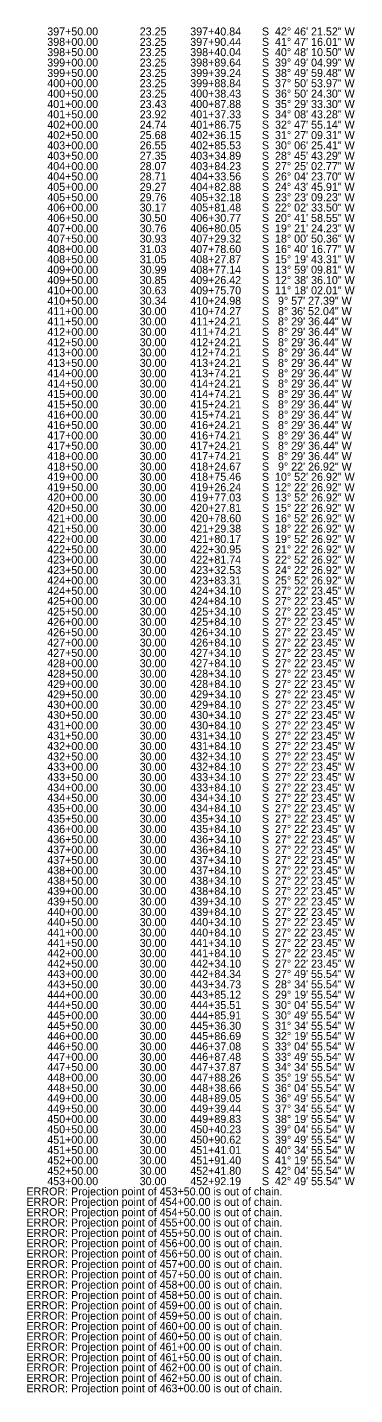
# Model space of a CAD drawing. Extents: x 1602163 to 1612907, y 1087635 to 1096265.
# Drawn here: x 1602163 to 1602409, y 1094083 to 1095108 of the extents above; entities that cross this region are included whole.
import ezdxf

# ---------------------------------------------------------------- set-up
doc = ezdxf.new("R2010")
doc.units = 0
doc.layers.add('RD_SHT_TX', color=7, linetype='Continuous')

msp = doc.modelspace()

# ---------------------------------------------------------------- texts
at = {"layer": 'RD_SHT_TX'}
for s, p in [('       397+50.00              23.25        397+40.84       S  42° 46\' 21.52" W  ', (1602162.4, 1095102.2)), ('       398+00.00              23.25        397+90.44       S  41° 47\' 16.01" W  ', (1602162.4, 1095094.4)), ('       398+50.00              23.25        398+40.04       S  40° 48\' 10.50" W  ', (1602162.4, 1095086.7)), ('       399+00.00              23.25        398+89.64       S  39° 49\' 04.99" W  ', (1602162.4, 1095078.9)), ('       399+50.00              23.25        399+39.24       S  38° 49\' 59.48" W  ', (1602162.4, 1095071.1)), ('       400+00.00              23.25        399+88.84       S  37° 50\' 53.97" W  ', (1602162.4, 1095063.4)), ('       400+50.00              23.25        400+38.43       S  36° 50\' 24.30" W  ', (1602162.4, 1095055.6)), ('       401+00.00              23.43        400+87.88       S  35° 29\' 33.30" W  ', (1602162.4, 1095047.8)), ('       401+50.00              23.92        401+37.33       S  34° 08\' 43.28" W  ', (1602162.4, 1095040.1)), ('       402+00.00              24.74        401+86.75       S  32° 47\' 55.14" W  ', (1602162.4, 1095032.3)), ('       402+50.00              25.68        402+36.15       S  31° 27\' 09.31" W  ', (1602162.4, 1095024.5)), ('       403+00.00              26.55        402+85.53       S  30° 06\' 25.41" W  ', (1602162.4, 1095016.8)), ('       403+50.00              27.35        403+34.89       S  28° 45\' 43.29" W  ', (1602162.4, 1095009)), ('       404+00.00              28.07        403+84.23       S  27° 25\' 02.77" W  ', (1602162.4, 1095001.2)), ('       404+50.00              28.71        404+33.56       S  26° 04\' 23.70" W  ', (1602162.4, 1094993.5)), ('       405+00.00              29.27        404+82.88       S  24° 43\' 45.91" W  ', (1602162.4, 1094985.7)), ('       405+50.00              29.76        405+32.18       S  23° 23\' 09.23" W  ', (1602162.4, 1094977.9)), ('       406+00.00              30.17        405+81.48       S  22° 02\' 33.50" W  ', (1602162.4, 1094970.2)), ('       406+50.00              30.50        406+30.77       S  20° 41\' 58.55" W  ', (1602162.4, 1094962.4)), ('       407+00.00              30.76        406+80.05       S  19° 21\' 24.23" W  ', (1602162.4, 1094954.6)), ('       407+50.00              30.93        407+29.32       S  18° 00\' 50.36" W  ', (1602162.4, 1094946.9)), ('       408+00.00              31.03        407+78.60       S  16° 40\' 16.77" W  ', (1602162.4, 1094939.1)), ('       408+50.00              31.05        408+27.87       S  15° 19\' 43.31" W  ', (1602162.4, 1094931.4)), ('       409+00.00              30.99        408+77.14       S  13° 59\' 09.81" W  ', (1602162.4, 1094923.6)), ('       409+50.00              30.85        409+26.42       S  12° 38\' 36.10" W  ', (1602162.4, 1094915.8)), ('       410+00.00              30.63        409+75.70       S  11° 18\' 02.01" W  ', (1602162.4, 1094908.1)), ('       410+50.00              30.34        410+24.98       S   9° 57\' 27.39" W  ', (1602162.4, 1094900.3)), ('       411+00.00              30.00        410+74.27       S   8° 36\' 52.04" W  ', (1602162.4, 1094892.5)), ('       411+50.00              30.00        411+24.21       S   8° 29\' 36.44" W  ', (1602162.4, 1094884.8)), ('       412+00.00              30.00        411+74.21       S   8° 29\' 36.44" W  ', (1602162.4, 1094877)), ('       412+50.00              30.00        412+24.21       S   8° 29\' 36.44" W  ', (1602162.4, 1094869.2)), ('       413+00.00              30.00        412+74.21       S   8° 29\' 36.44" W  ', (1602162.4, 1094861.5)), ('       413+50.00              30.00        413+24.21       S   8° 29\' 36.44" W  ', (1602162.4, 1094853.7)), ('       414+00.00              30.00        413+74.21       S   8° 29\' 36.44" W  ', (1602162.4, 1094845.9)), ('       414+50.00              30.00        414+24.21       S   8° 29\' 36.44" W  ', (1602162.4, 1094838.2)), ('       415+00.00              30.00        414+74.21       S   8° 29\' 36.44" W  ', (1602162.4, 1094830.4)), ('       415+50.00              30.00        415+24.21       S   8° 29\' 36.44" W  ', (1602162.4, 1094822.6)), ('       416+00.00              30.00        415+74.21       S   8° 29\' 36.44" W  ', (1602162.4, 1094814.9)), ('       416+50.00              30.00        416+24.21       S   8° 29\' 36.44" W  ', (1602162.4, 1094807.1)), ('       417+00.00              30.00        416+74.21       S   8° 29\' 36.44" W  ', (1602162.4, 1094799.3)), ('       417+50.00              30.00        417+24.21       S   8° 29\' 36.44" W  ', (1602162.4, 1094791.6)), ('       418+00.00              30.00        417+74.21       S   8° 29\' 36.44" W  ', (1602162.4, 1094783.8)), ('       418+50.00              30.00        418+24.67       S   9° 22\' 26.92" W  ', (1602162.4, 1094776)), ('       419+00.00              30.00        418+75.46       S  10° 52\' 26.92" W  ', (1602162.4, 1094768.3)), ('       419+50.00              30.00        419+26.24       S  12° 22\' 26.92" W  ', (1602162.4, 1094760.5)), ('       420+00.00              30.00        419+77.03       S  13° 52\' 26.92" W  ', (1602162.4, 1094752.8)), ('       420+50.00              30.00        420+27.81       S  15° 22\' 26.92" W  ', (1602162.4, 1094745)), ('       421+00.00              30.00        420+78.60       S  16° 52\' 26.92" W  ', (1602162.4, 1094737.2)), ('       421+50.00              30.00        421+29.38       S  18° 22\' 26.92" W  ', (1602162.4, 1094729.5)), ('       422+00.00              30.00        421+80.17       S  19° 52\' 26.92" W  ', (1602162.4, 1094721.7)), ('       422+50.00              30.00        422+30.95       S  21° 22\' 26.92" W  ', (1602162.4, 1094713.9)), ('       423+00.00              30.00        422+81.74       S  22° 52\' 26.92" W  ', (1602162.4, 1094706.2)), ('       423+50.00              30.00        423+32.53       S  24° 22\' 26.92" W  ', (1602162.4, 1094698.4)), ('       424+00.00              30.00        423+83.31       S  25° 52\' 26.92" W  ', (1602162.4, 1094690.6)), ('       424+50.00              30.00        424+34.10       S  27° 22\' 23.45" W  ', (1602162.4, 1094682.9)), ('       425+00.00              30.00        424+84.10       S  27° 22\' 23.45" W  ', (1602162.4, 1094675.1)), ('       425+50.00              30.00        425+34.10       S  27° 22\' 23.45" W  ', (1602162.4, 1094667.3)), ('       426+00.00              30.00        425+84.10       S  27° 22\' 23.45" W  ', (1602162.4, 1094659.6)), ('       426+50.00              30.00        426+34.10       S  27° 22\' 23.45" W  ', (1602162.4, 1094651.8)), ('       427+00.00              30.00        426+84.10       S  27° 22\' 23.45" W  ', (1602162.4, 1094644)), ('       427+50.00              30.00        427+34.10       S  27° 22\' 23.45" W  ', (1602162.4, 1094636.3)), ('       428+00.00              30.00        427+84.10       S  27° 22\' 23.45" W  ', (1602162.4, 1094628.5)), ('       428+50.00              30.00        428+34.10       S  27° 22\' 23.45" W  ', (1602162.4, 1094620.7)), ('       429+00.00              30.00        428+84.10       S  27° 22\' 23.45" W  ', (1602162.4, 1094613)), ('       429+50.00              30.00        429+34.10       S  27° 22\' 23.45" W  ', (1602162.4, 1094605.2)), ('       430+00.00              30.00        429+84.10       S  27° 22\' 23.45" W  ', (1602162.4, 1094597.4)), ('       430+50.00              30.00        430+34.10       S  27° 22\' 23.45" W  ', (1602162.4, 1094589.7)), ('       431+00.00              30.00        430+84.10       S  27° 22\' 23.45" W  ', (1602162.4, 1094581.9)), ('       431+50.00              30.00        431+34.10       S  27° 22\' 23.45" W  ', (1602162.4, 1094574.2)), ('       432+00.00              30.00        431+84.10       S  27° 22\' 23.45" W  ', (1602162.4, 1094566.4)), ('       432+50.00              30.00        432+34.10       S  27° 22\' 23.45" W  ', (1602162.4, 1094558.6)), ('       433+00.00              30.00        432+84.10       S  27° 22\' 23.45" W  ', (1602162.4, 1094550.9)), ('       433+50.00              30.00        433+34.10       S  27° 22\' 23.45" W  ', (1602162.4, 1094543.1)), ('       434+00.00              30.00        433+84.10       S  27° 22\' 23.45" W  ', (1602162.4, 1094535.3)), ('       434+50.00              30.00        434+34.10       S  27° 22\' 23.45" W  ', (1602162.4, 1094527.6)), ('       435+00.00              30.00        434+84.10       S  27° 22\' 23.45" W  ', (1602162.4, 1094519.8)), ('       435+50.00              30.00        435+34.10       S  27° 22\' 23.45" W  ', (1602162.4, 1094512)), ('       436+00.00              30.00        435+84.10       S  27° 22\' 23.45" W  ', (1602162.4, 1094504.3)), ('       436+50.00              30.00        436+34.10       S  27° 22\' 23.45" W  ', (1602162.4, 1094496.5)), ('       437+00.00              30.00        436+84.10       S  27° 22\' 23.45" W  ', (1602162.4, 1094488.7)), ('       437+50.00              30.00        437+34.10       S  27° 22\' 23.45" W  ', (1602162.4, 1094481)), ('       438+00.00              30.00        437+84.10       S  27° 22\' 23.45" W  ', (1602162.4, 1094473.2)), ('       438+50.00              30.00        438+34.10       S  27° 22\' 23.45" W  ', (1602162.4, 1094465.4)), ('       439+00.00              30.00        438+84.10       S  27° 22\' 23.45" W  ', (1602162.4, 1094457.7)), ('       439+50.00              30.00        439+34.10       S  27° 22\' 23.45" W  ', (1602162.4, 1094449.9)), ('       440+00.00              30.00        439+84.10       S  27° 22\' 23.45" W  ', (1602162.4, 1094442.1)), ('       440+50.00              30.00        440+34.10       S  27° 22\' 23.45" W  ', (1602162.4, 1094434.4)), ('       441+00.00              30.00        440+84.10       S  27° 22\' 23.45" W  ', (1602162.4, 1094426.6)), ('       441+50.00              30.00        441+34.10       S  27° 22\' 23.45" W  ', (1602162.4, 1094418.8)), ('       442+00.00              30.00        441+84.10       S  27° 22\' 23.45" W  ', (1602162.4, 1094411.1)), ('       442+50.00              30.00        442+34.10       S  27° 22\' 23.45" W  ', (1602162.4, 1094403.3)), ('       443+00.00              30.00        442+84.34       S  27° 49\' 55.54" W  ', (1602162.4, 1094395.6)), ('       443+50.00              30.00        443+34.73       S  28° 34\' 55.54" W  ', (1602162.4, 1094387.8)), ('       444+00.00              30.00        443+85.12       S  29° 19\' 55.54" W  ', (1602162.4, 1094380)), ('       444+50.00              30.00        444+35.51       S  30° 04\' 55.54" W  ', (1602162.4, 1094372.3)), ('       445+00.00              30.00        444+85.91       S  30° 49\' 55.54" W  ', (1602162.4, 1094364.5)), ('       445+50.00              30.00        445+36.30       S  31° 34\' 55.54" W  ', (1602162.4, 1094356.7)), ('       446+00.00              30.00        445+86.69       S  32° 19\' 55.54" W  ', (1602162.4, 1094349)), ('       446+50.00              30.00        446+37.08       S  33° 04\' 55.54" W  ', (1602162.4, 1094341.2)), ('       447+00.00              30.00        446+87.48       S  33° 49\' 55.54" W  ', (1602162.4, 1094333.4)), ('       447+50.00              30.00        447+37.87       S  34° 34\' 55.54" W  ', (1602162.4, 1094325.7)), ('       448+00.00              30.00        447+88.26       S  35° 19\' 55.54" W  ', (1602162.4, 1094317.9)), ('       448+50.00              30.00        448+38.66       S  36° 04\' 55.54" W  ', (1602162.4, 1094310.1)), ('       449+00.00              30.00        448+89.05       S  36° 49\' 55.54" W  ', (1602162.4, 1094302.4)), ('       449+50.00              30.00        449+39.44       S  37° 34\' 55.54" W  ', (1602162.4, 1094294.6)), ('       450+00.00              30.00        449+89.83       S  38° 19\' 55.54" W  ', (1602162.4, 1094286.8)), ('       450+50.00              30.00        450+40.23       S  39° 04\' 55.54" W  ', (1602162.4, 1094279.1)), ('       451+00.00              30.00        450+90.62       S  39° 49\' 55.54" W  ', (1602162.4, 1094271.3)), ('       451+50.00              30.00        451+41.01       S  40° 34\' 55.54" W  ', (1602162.4, 1094263.5)), ('       452+00.00              30.00        451+91.40       S  41° 19\' 55.54" W  ', (1602162.4, 1094255.8)), ('       452+50.00              30.00        452+41.80       S  42° 04\' 55.54" W  ', (1602162.4, 1094248)), ('       453+00.00              30.00        452+92.19       S  42° 49\' 55.54" W  ', (1602162.4, 1094240.2)), ('ERROR: Projection point of 453+50.00 is out of chain.', (1602162.4, 1094232.5)), ('ERROR: Projection point of 454+00.00 is out of chain.', (1602162.4, 1094224.7)), ('ERROR: Projection point of 454+50.00 is out of chain.', (1602162.4, 1094216.9)), ('ERROR: Projection point of 455+00.00 is out of chain.', (1602162.4, 1094209.2)), ('ERROR: Projection point of 455+50.00 is out of chain.', (1602162.4, 1094201.4)), ('ERROR: Projection point of 456+00.00 is out of chain.', (1602162.4, 1094193.7)), ('ERROR: Projection point of 456+50.00 is out of chain.', (1602162.4, 1094185.9)), ('ERROR: Projection point of 457+00.00 is out of chain.', (1602162.4, 1094178.1)), ('ERROR: Projection point of 457+50.00 is out of chain.', (1602162.4, 1094170.4)), ('ERROR: Projection point of 458+00.00 is out of chain.', (1602162.4, 1094162.6)), ('ERROR: Projection point of 458+50.00 is out of chain.', (1602162.4, 1094154.8)), ('ERROR: Projection point of 459+00.00 is out of chain.', (1602162.4, 1094147.1)), ('ERROR: Projection point of 459+50.00 is out of chain.', (1602162.4, 1094139.3)), ('ERROR: Projection point of 460+00.00 is out of chain.', (1602162.4, 1094131.5)), ('ERROR: Projection point of 460+50.00 is out of chain.', (1602162.4, 1094123.8)), ('ERROR: Projection point of 461+00.00 is out of chain.', (1602162.4, 1094116)), ('ERROR: Projection point of 461+50.00 is out of chain.', (1602162.4, 1094108.2)), ('ERROR: Projection point of 462+00.00 is out of chain.', (1602162.4, 1094100.5)), ('ERROR: Projection point of 462+50.00 is out of chain.', (1602162.4, 1094092.7)), ('ERROR: Projection point of 463+00.00 is out of chain.', (1602162.4, 1094084.9))]:
    msp.add_text(s, height=6, dxfattribs=at).set_placement(p)

doc.saveas('drawing.dxf')
